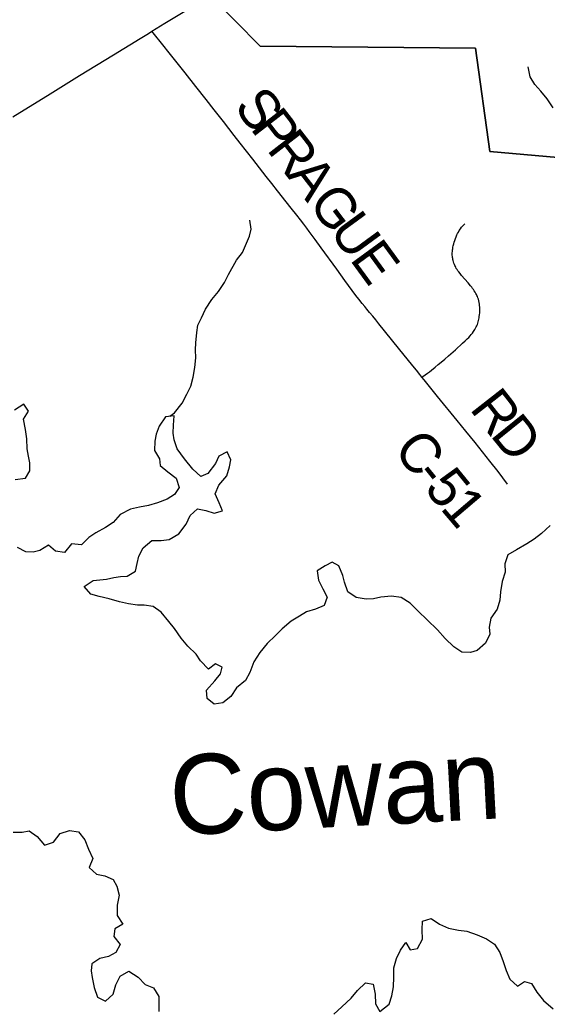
# Model space of a CAD drawing. Extents: x 0 to 34, y 0 to 22.
# Drawn here: x 2.83 to 3.583, y 18.468 to 19.877 of the extents above; entities that cross this region are included whole.
import ezdxf

# ---------------------------------------------------------------- set-up
doc = ezdxf.new("R2010")
doc.units = 0
for name, color, linetype in [('GM_X_County_Road', 7, 'Continuous'), ('GM_X_County_Road_Text', 7, 'Continuous'), ('GM_X_Major_Lake', 7, 'Continuous'), ('GM_X_Major_Lake_Text', 7, 'Continuous'), ('GM_X_Minor_River', 7, 'Continuous'), ('GM_X_State_Route', 7, 'Continuous'), ('GM_X_Township_Road', 7, 'Continuous')]:
    doc.layers.add(name, color=color, linetype=linetype)

msp = doc.modelspace()

# ---------------------------------------------------------------- linework, layer by layer
at = {"layer": 'GM_X_County_Road'}
for points in [[(3.4042, 19.3671), (3.401, 19.371), (3.3963, 19.377), (3.3911, 19.3835), (3.3708, 19.4088), (3.3428, 19.4435), (3.3382, 19.4492), (3.3341, 19.454), (3.3295, 19.4593), (3.3256, 19.464), (3.3225, 19.4678), (3.3189, 19.4721), (3.3141, 19.4783), (3.3098, 19.4839), (3.3045, 19.491), (3.2943, 19.505), (3.2826, 19.5211), (3.2606, 19.5516), (3.2518, 19.5637), (3.2435, 19.5748), (3.2398, 19.5797), (3.2356, 19.5856), (3.2308, 19.5918), (3.2255, 19.5985), (3.2178, 19.6082), (3.2104, 19.6174), (3.1979, 19.6332), (3.1899, 19.6436), (3.1819, 19.6536), (3.1628, 19.6781), (3.1449, 19.7011), (3.1365, 19.7118), (3.121, 19.732), (3.108, 19.7487), (3.0965, 19.7634), (3.0818, 19.7819), (3.0663, 19.8013), (3.0512, 19.8202), (3.0436, 19.8296), (3.0346, 19.841), (3.0208, 19.8585), (3.0191, 19.8607)], [(3.5264, 19.2147), (3.5127, 19.2325), (3.5008, 19.2475), (3.4799, 19.2738), (3.4666, 19.2901), (3.4542, 19.3056), (3.4265, 19.3396), (3.4073, 19.3632), (3.4042, 19.3671)]]:
    msp.add_lwpolyline(points, dxfattribs=at)
at = {"layer": 'GM_X_Major_Lake'}
for points in [[(2.8239, 19.221), (2.8388, 19.2232), (2.8448, 19.2337), (2.8447, 19.245), (2.8431, 19.2546), (2.8411, 19.2649), (2.8404, 19.2793), (2.8389, 19.2926), (2.8359, 19.3071), (2.843, 19.3187), (2.8361, 19.3287), (2.823, 19.32)], [(3.0321, 19.134), (3.0438, 19.1356), (3.0573, 19.1439), (3.068, 19.1573), (3.0736, 19.17), (3.0841, 19.1796), (3.0958, 19.177), (3.1078, 19.1733), (3.1196, 19.1767), (3.1147, 19.1879), (3.109, 19.2009), (3.1143, 19.2133), (3.126, 19.2266), (3.1298, 19.2394), (3.1316, 19.2492), (3.1262, 19.2608), (3.1143, 19.2546), (3.1098, 19.2441), (3.0988, 19.23), (3.0888, 19.2254), (3.0774, 19.2359), (3.0657, 19.2507), (3.0551, 19.265), (3.0506, 19.2777), (3.0493, 19.2872), (3.05, 19.2989), (3.0508, 19.3122), (3.0386, 19.3106), (3.0292, 19.2972), (3.025, 19.286), (3.0232, 19.2758), (3.0229, 19.2625), (3.0297, 19.2509), (3.0306, 19.241), (3.0417, 19.232), (3.0536, 19.2233), (3.0577, 19.2096), (3.051, 19.1999), (3.0406, 19.1933), (3.0268, 19.188), (3.0142, 19.1842), (3.0012, 19.1819), (2.9883, 19.1789), (2.9737, 19.1713), (2.9635, 19.1598), (2.953, 19.1529), (2.9392, 19.1453), (2.9291, 19.1384), (2.9186, 19.128), (2.9043, 19.1296), (2.8944, 19.1173), (2.8816, 19.1192), (2.8713, 19.1275), (2.8589, 19.1202), (2.8494, 19.1178), (2.8392, 19.1181), (2.8272, 19.1241)], [(3.5869, 19.1554), (3.5748, 19.1444), (3.5643, 19.1363), (3.5539, 19.1294), (3.5389, 19.1211), (3.5266, 19.1139), (3.5224, 19.1011), (3.5228, 19.0889), (3.5187, 19.0758), (3.5164, 19.061), (3.5153, 19.0493), (3.5115, 19.0361), (3.5024, 19.0235), (3.5001, 19.0106), (3.501, 19.0004), (3.4946, 18.9877), (3.4829, 18.9774), (3.4733, 18.9746), (3.4609, 18.9749), (3.4497, 18.9824), (3.4372, 18.9946), (3.4265, 19.007), (3.4118, 19.0211), (3.3989, 19.0332), (3.3875, 19.0449), (3.3744, 19.0528), (3.3609, 19.0547), (3.3457, 19.0532), (3.335, 19.0509), (3.3244, 19.0504), (3.3104, 19.0527), (3.2985, 19.061), (3.2936, 19.0748), (3.2913, 19.0843), (3.2856, 19.0982), (3.2759, 19.1034), (3.2663, 19.0979), (3.2547, 19.091), (3.2566, 19.0777), (3.2627, 19.0654), (3.2692, 19.0535), (3.2646, 19.0414), (3.2524, 19.0361), (3.2394, 19.0323), (3.2297, 19.0265), (3.2174, 19.0192), (3.2046, 19.0082), (3.1952, 18.9986), (3.1835, 18.9872), (3.1729, 18.9746), (3.1646, 18.9611), (3.1589, 18.9461), (3.1525, 18.9345), (3.1397, 18.9239), (3.1317, 18.9116), (3.1201, 18.9028), (3.1076, 18.9009), (3.098, 18.9087), (3.0968, 18.9209), (3.1089, 18.9342), (3.1168, 18.9439), (3.1193, 18.9537), (3.1096, 18.9581), (3.0995, 18.9508), (3.0881, 18.9625), (3.082, 18.9722), (3.0702, 18.9835), (3.0607, 18.9951), (3.0512, 19.0087), (3.0431, 19.0188), (3.0322, 19.032), (3.0206, 19.0399), (3.0078, 19.0421), (2.9984, 19.042), (2.9855, 19.0439), (2.9727, 19.0469), (2.9581, 19.0511), (2.9438, 19.0545), (2.9318, 19.0575), (2.9222, 19.0684), (2.9353, 19.0771), (2.9448, 19.078), (2.9543, 19.0793), (2.9646, 19.0816), (2.9741, 19.0829), (2.9836, 19.0834), (2.9956, 19.0906), (2.9982, 19.1012), (3.0004, 19.1117), (3.0064, 19.1237), (3.0188, 19.1344), (3.0321, 19.134)], [(2.8213, 18.7184), (2.8341, 18.718), (2.844, 18.72), (2.8552, 18.7121), (2.8658, 18.6997), (2.8784, 18.7039), (2.8883, 18.7165), (2.9013, 18.7207), (2.9141, 18.7185), (2.9232, 18.7072), (2.9285, 18.6938), (2.9346, 18.6807), (2.9297, 18.6676), (2.94, 18.6582), (2.9517, 18.656), (2.9637, 18.6507), (2.9691, 18.6411), (2.9725, 18.6281), (2.9694, 18.6141), (2.9694, 18.5993), (2.9774, 18.587), (2.9662, 18.5804), (2.9647, 18.5695), (2.9735, 18.5582), (2.9675, 18.5466)], [(3.2786, 18.4584), (3.2899, 18.469), (3.3031, 18.4812), (3.3122, 18.4923), (3.3238, 18.5034), (3.3348, 18.5012), (3.3374, 18.4871), (3.3378, 18.4734), (3.3439, 18.4622), (3.3574, 18.4729), (3.3612, 18.4849), (3.3638, 18.4977), (3.3639, 18.5114), (3.3642, 18.5246), (3.368, 18.5378), (3.3737, 18.5498), (3.3812, 18.561), (3.3873, 18.5502), (3.398, 18.5525), (3.4048, 18.5656), (3.4044, 18.5789), (3.4048, 18.5914), (3.4174, 18.5949), (3.4293, 18.587), (3.442, 18.5813), (3.4563, 18.5786), (3.4684, 18.5768), (3.483, 18.5718), (3.4961, 18.5661), (3.5076, 18.5586), (3.5153, 18.5466), (3.5202, 18.5336), (3.5244, 18.521), (3.5297, 18.5087), (3.5404, 18.4985), (3.5504, 18.5051), (3.5606, 18.5025), (3.5678, 18.4898), (3.5777, 18.4781), (3.5914, 18.4664)], [(2.9675, 18.5466), (2.9571, 18.5409), (2.9449, 18.5382), (2.9333, 18.5305), (2.9323, 18.5203), (2.9339, 18.5108), (2.9365, 18.4967), (2.9414, 18.4829), (2.953, 18.4772), (2.9639, 18.4872), (2.9677, 18.5004), (2.9737, 18.5127), (2.986, 18.52), (2.9994, 18.5112), (3.0094, 18.5011), (3.0214, 18.4962), (3.029, 18.4839), (3.029, 18.4729), (3.0287, 18.4626)]]:
    msp.add_lwpolyline(points, dxfattribs=at)
at = {"layer": 'GM_X_Minor_River'}
for points in [[(3.5911, 19.7512), (3.5826, 19.7643), (3.5738, 19.7751), (3.5653, 19.7847), (3.5587, 19.7958), (3.5559, 19.8099)], [(3.0445, 19.3114), (3.051, 19.3165), (3.0623, 19.3299), (3.069, 19.3431), (3.0745, 19.3543), (3.0778, 19.3672), (3.08, 19.3812), (3.0818, 19.3948), (3.0813, 19.4062), (3.0815, 19.4164), (3.0829, 19.4308), (3.0847, 19.4414), (3.0898, 19.4519), (3.0954, 19.4643), (3.1047, 19.4778), (3.1141, 19.4894), (3.1226, 19.5021), (3.1282, 19.5138), (3.1396, 19.534), (3.1482, 19.5452), (3.1525, 19.555), (3.1581, 19.5682), (3.1606, 19.5784), (3.1586, 19.5913)]]:
    msp.add_lwpolyline(points, dxfattribs=at)
at = {"layer": 'GM_X_State_Route'}
msp.add_line((3.014, 19.8575), (3.0191, 19.8607), dxfattribs=at)
for points in [[(3.0191, 19.8607), (3.0376, 19.8721), (3.0732, 19.8937), (3.1021, 19.9115)], [(2.8207, 19.7386), (2.8741, 19.7715), (2.9159, 19.7973), (2.964, 19.8269), (3.0022, 19.8502), (3.014, 19.8575)]]:
    msp.add_lwpolyline(points, dxfattribs=at)
at = {"layer": 'GM_X_Township_Road'}
msp.add_lwpolyline([(4.4664, 20.9), (2.1, 20.9), (2.1, 20.7431), (2.3144, 20.5665), (3.1019, 19.912), (3.1735, 19.8394), (3.4805, 19.8366), (3.501, 19.6889), (4.4654, 19.6041), (4.4849, 19.6021), (4.4684, 20.7448)], close=True, dxfattribs=at)
for points in [[(3.7787, 17.0143), (3.7921, 17.074), (3.9903, 17.6899), (4.0744, 17.9948), (4.1901, 18.4135), (4.1943, 18.4289), (4.2897, 18.7747), (4.3389, 18.9527), (4.4789, 19.5742), (4.4849, 19.6021), (4.4654, 19.6041), (3.501, 19.6889), (3.4805, 19.8366), (3.1735, 19.8394), (3.1019, 19.912), (2.3144, 20.5665), (2.1, 20.7431), (2.1, 15.597), (2.2517, 15.5643), (3.1228, 15.3686), (3.3385, 15.3189), (3.6691, 16.5264), (3.7277, 16.7873)], [(3.4042, 19.3671), (3.4055, 19.3681), (3.4089, 19.3704), (3.4121, 19.3727), (3.415, 19.3748), (3.418, 19.3772), (3.4232, 19.3815), (3.4275, 19.3851), (3.4316, 19.3885), (3.4366, 19.3929), (3.442, 19.3977), (3.4518, 19.4064), (3.4621, 19.4157), (3.4658, 19.419), (3.4688, 19.4217), (3.4709, 19.4239), (3.4728, 19.4261), (3.4745, 19.428), (3.4762, 19.4302), (3.4778, 19.4323), (3.4796, 19.4351), (3.4806, 19.437), (3.4817, 19.4391), (3.4824, 19.4404), (3.4833, 19.4425), (3.484, 19.4444), (3.4845, 19.4461), (3.485, 19.448), (3.4854, 19.4499), (3.4857, 19.4518), (3.486, 19.4536), (3.4862, 19.4559), (3.4865, 19.4588), (3.4866, 19.4624), (3.4866, 19.4651), (3.4866, 19.4672), (3.4864, 19.4694), (3.4862, 19.4714), (3.4857, 19.4739), (3.4852, 19.4761), (3.4846, 19.4785), (3.4839, 19.4804), (3.4832, 19.4825), (3.4826, 19.4838), (3.482, 19.4851), (3.4811, 19.4867), (3.4801, 19.4884), (3.4788, 19.4904), (3.4776, 19.4921), (3.4765, 19.4937), (3.4751, 19.4955), (3.4732, 19.4977), (3.4699, 19.5016), (3.4608, 19.5124), (3.4588, 19.5149), (3.4568, 19.5173), (3.4555, 19.519), (3.4543, 19.5207), (3.4532, 19.5224), (3.4524, 19.524), (3.4518, 19.5252), (3.4511, 19.5266), (3.4505, 19.5281), (3.4498, 19.5297), (3.4492, 19.5315), (3.4487, 19.5334), (3.4483, 19.5349), (3.4481, 19.5363), (3.4478, 19.538), (3.4477, 19.5394), (3.4475, 19.541), (3.4474, 19.5428), (3.4474, 19.5443), (3.4476, 19.5469), (3.4478, 19.5487), (3.448, 19.5503), (3.4483, 19.5524), (3.4488, 19.5546), (3.4496, 19.5572), (3.4503, 19.5597), (3.4512, 19.5623), (3.4522, 19.5651), (3.4531, 19.5674), (3.4541, 19.57), (3.455, 19.5722), (3.4561, 19.5741), (3.4573, 19.5762), (3.4591, 19.5787), (3.4608, 19.581), (3.463, 19.5835), (3.4652, 19.5858)]]:
    msp.add_lwpolyline(points, dxfattribs=at)

# ---------------------------------------------------------------- texts
at = {"layer": 'GM_X_County_Road_Text'}
for s, rotation, p in [('S', 307.7727, (3.1347, 19.7524)), ('P', 307.7727, (3.1582, 19.7221)), ('R', 307.7723, (3.1817, 19.6918)), ('A', 307.71, (3.2103, 19.6549)), ('G', 307.02, (3.2407, 19.6155)), ('U', 306.1894, (3.2707, 19.5758)), ('E', 306.1388, (3.3002, 19.5354)), ('R', 308.0183, (3.471, 19.322)), ('D', 308.943, (3.5004, 19.2845)), ('C', 308.5242, (3.362, 19.2635)), ('-', 308.6894, (3.3911, 19.2268)), ('5', 309.1597, (3.4061, 19.2082)), ('1', 310.4091, (3.429, 19.18))]:
    msp.add_text(s, height=0.0568, rotation=rotation, dxfattribs=at).set_placement(p)
at = {"layer": 'GM_X_Major_Lake_Text'}
msp.add_text('Cowan', height=0.11363, rotation=2.9989, dxfattribs=at).set_placement((3.047, 18.7133))

doc.saveas('drawing.dxf')
